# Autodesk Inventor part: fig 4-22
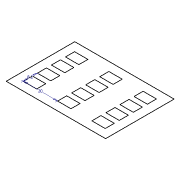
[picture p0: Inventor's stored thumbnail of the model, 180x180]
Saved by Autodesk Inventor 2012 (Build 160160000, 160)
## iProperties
Created: 2004-05
Part Number: fig 4-22
Document SubType Name: Modeling
Designer: CADCIM Technologies
Manufacturer: Standard
Standards Organization: Custom
Density: 1 g/cm^3
Material: Default
Author: CADCIM Technologies
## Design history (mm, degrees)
sketch "Sketch1"
  geometry: L1 (7.752, 6.176)-(65.752, 6.176); L2 (65.752, 6.176)-(65.752, 46.176); L3 (65.752, 46.176)-(7.752, 46.176); L4 (7.752, 46.176)-(7.752, 6.176); L5 (12.752, 11.176)-(20.543, 11.176); L6 (20.543, 11.176)-(20.543, 16.473); L7 (20.543, 16.473)-(12.752, 16.473); L8 (12.752, 16.473)-(12.752, 11.176); L9 (32.752, 11.176)-(40.543, 11.176); L10 (40.543, 11.176)-(40.543, 16.473); L11 (40.543, 16.473)-(32.752, 16.473); L12 (32.752, 16.473)-(32.752, 11.176); L13 (52.752, 11.176)-(60.543, 11.176); L14 (60.543, 11.176)-(60.543, 16.473); L15 (60.543, 16.473)-(52.752, 16.473); L16 (52.752, 16.473)-(52.752, 11.176); L17 (12.752, 19.376)-(20.543, 19.376); L18 (20.543, 19.376)-(20.543, 24.673); L19 (20.543, 24.673)-(12.752, 24.673); L20 (12.752, 24.673)-(12.752, 19.376); L21 (32.752, 19.376)-(40.543, 19.376); L22 (40.543, 19.376)-(40.543, 24.673); L23 (40.543, 24.673)-(32.752, 24.673); L24 (32.752, 24.673)-(32.752, 19.376); L25 (52.752, 19.376)-(60.543, 19.376); L26 (60.543, 19.376)-(60.543, 24.673); L27 (60.543, 24.673)-(52.752, 24.673); L28 (52.752, 24.673)-(52.752, 19.376); L29 (12.752, 27.576)-(20.543, 27.576); L30 (20.543, 27.576)-(20.543, 32.873); L31 (20.543, 32.873)-(12.752, 32.873); L32 (12.752, 32.873)-(12.752, 27.576); L33 (32.752, 27.576)-(40.543, 27.576); L34 (40.543, 27.576)-(40.543, 32.873); L35 (40.543, 32.873)-(32.752, 32.873); L36 (32.752, 32.873)-(32.752, 27.576); L37 (52.752, 27.576)-(60.543, 27.576); L38 (60.543, 27.576)-(60.543, 32.873); L39 (60.543, 32.873)-(52.752, 32.873); L40 (52.752, 32.873)-(52.752, 27.576); L41 (12.752, 35.776)-(20.543, 35.776); L42 (20.543, 35.776)-(20.543, 41.073); L43 (20.543, 41.073)-(12.752, 41.073); L44 (12.752, 41.073)-(12.752, 35.776); L45 (32.752, 35.776)-(40.543, 35.776); L46 (40.543, 35.776)-(40.543, 41.073); L47 (40.543, 41.073)-(32.752, 41.073); L48 (32.752, 41.073)-(32.752, 35.776); L49 (52.752, 35.776)-(60.543, 35.776); L50 (60.543, 35.776)-(60.543, 41.073); L51 (60.543, 41.073)-(52.752, 41.073); L52 (52.752, 41.073)-(52.752, 35.776)
  constraints: 104 end point, 4 parallel, 3 horizontal, 2 perpendicular, 1 vertical, 88 other
  dimensions: "d14" = 20 distance of L5.start L9.start; "d17" = 8.2 distance of L5.start L17.start
